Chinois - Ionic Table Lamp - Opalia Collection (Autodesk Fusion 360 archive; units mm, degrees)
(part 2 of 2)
create_component "CreateComponent4"
create_component "CreateComponent5"
create_component "CreateComponent6"
create_component "CreateComponent7"
create_component "CreateComponent8"
remove_body "RemoveBody1"
create_component "CreateComponent9"
create_component "CreateComponent10"
create_component "CreateComponent11"
create_component "CreateComponent12"
create_component "CreateComponent13"
create_component "CreateComponent14"
create_component "CreateComponent15"
create_component "CreateComponent16"
create_component "CreateComponent17"
create_component "CreateComponent18"
remove_body "RemoveBody6"
create_component "CreateComponent19"
create_component "CreateComponent20"
create_component "CreateComponent21"
create_component "CreateComponent22"
create_component "CreateComponent23"
named bodies: "Marble Base", "Rotary Switch", "Coiled - SVT (Blk Fabric)", "Glass Globe", "Metal Housing", "Metal Socket Cover", "Porcelain Socket", "Brass Dial - Dimmer Knob", "Solitaire Petite", "Facet Petite", "Body1", "Body2", "Plastic Insert", "Silicone Gasket", "Oculo Petite", "Balon v2", "Balon v3", "Trove - TL", "Trove - TL (1)", "Neoprene Pad", "2-Pole Plug End", "Rubber Grommet", "Chinois"

design "Trove - TL"
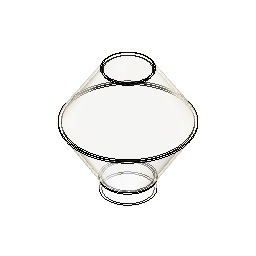
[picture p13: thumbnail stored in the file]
derived_base_feature "Derived Base Feature" bodies "Trove"
hole "Hole1" HoleDepth 88.9 HoleDiameter 44.45 TipAngle 118
sketch "Sketch1" plane through (0, 0, 0) normal (1, 0, 0) x axis (0, 1, 0)
  line L1 (0, 243.0601) -> (0, 247.8226)
  line L2 (-50.8, -12.7122) -> (-50.8, 10.9447)
  line L3 (0, -25.4) -> (0, 243.0601)
  line L4 (-46.0375, -12.7122) -> (-50.8, -12.7122)
  line L5 (-46.0375, -12.7122) -> (-46.0375, 12.3043)
  line L6 (-45.9716, 247.8226) -> (0, 247.8226)
  line L7 (-43.3841, 243.0601) -> (0, 243.0601)
  line L8 (-122.8321, 128.6352) -> (-51.757, 14.2971)
  line L9 (-117.1907, 128.5808) -> (-46.9945, 15.6567)
  line L10 (-48.6353, 246.3754) -> (-122.7993, 132.0392)
  line L11 (-46.0478, 241.6129) -> (-117.1579, 131.9848)
  arc A1 centre (-57.15, 10.9447) radius 6.35 clockwise from (-51.757, 14.2971) to (-50.8, 10.9447)
  arc A2 centre (-52.3875, 12.3043) radius 6.35 clockwise from (-46.9945, 15.6567) to (-46.0375, 12.3043)
  arc A3 centre (-114.4942, 130.257) radius 3.175 between (-117.1579, 131.9848) and (-117.1907, 128.5808)
  arc A4 centre (-120.1356, 130.3114) radius 3.175 between (-122.7993, 132.0392) and (-122.8321, 128.6352)
  arc A5 centre (-45.9716, 244.6476) radius 3.175 between (-45.9716, 247.8226) and (-48.6353, 246.3754)
  arc A6 centre (-43.3841, 239.8851) radius 3.175 clockwise from (-46.0478, 241.6129) to (-43.3841, 243.0601)
  point P3 (0, 247.8226)
  point P4 (0, 243.0601)
  vertical L1
  vertical L3
  tangent L5 A2
  perpendicular L1 L6
  perpendicular L1 L7
  tangent L11 A3
  tangent L9 A3
  tangent L10 A4
  tangent L8 A4
  equal A3 A4
  tangent L6 A5
  tangent L10 A5
  tangent L11 A6
  tangent L7 A6
  dimension "d8" distance P3 P4 = 4.7625
  dimension "d11" radius A2 = 6.35
  dimension "d15" radius A3 = 3.175
  dimension "d16" radius A5 = 3.175
  dimension "d17" radius A6 = 3.175
revolve "Revolve1" sketch "Sketch1" AlongAngle 180 bodies "Trove - TL"
revolve "Revolve2" sketch "Sketch1" AlongAngle -180
component_from_bodies "Body->Comp"
remove_body "RemoveBody2"
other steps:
base_feature "Base Feature" bodies "Trove - TL"
create_component "CreateComponent1"
remove_body "RemoveBody1"
named bodies: "Trove", "Trove - TL"

design "T9-5In"
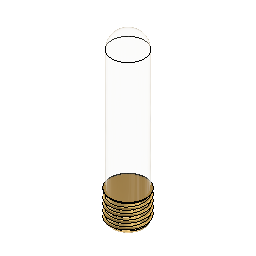
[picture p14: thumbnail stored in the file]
sketch "Sketch1" plane through (0, 0, 0) normal (0, 1, 0) x axis (1, 0, 0)
  line L1 (0, 0) -> (0, -127)
  line L2 (12.7, -127) -> (-12.7, -127)
  line L3 (12.7, -12.7) -> (12.7, -127)
  line L4 (-12.7, -127) -> (-12.7, -12.7)
  arc A1 centre (0, -12.7) radius 12.7 clockwise from (-12.7, -12.7) to (12.7, -12.7)
  point P1 (0, 0)
  point P3 (0, 0)
  coincident P1 P3
  vertical L1
  horizontal L2
  vertical L3
  vertical L4
revolve "Revolve1" sketch "Sketch1" AlongAngle 360 bodies "BU-T10-5-LED-120V"
derived_base_feature "Derived Base Feature" bodies "E26 Base"
move "Move1"
component_from_bodies "Body->Comp"
copy_paste "CutPaste"
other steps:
base_feature "Base Feature" bodies "BU-T10-5-LED-120V"
create_component "CreateComponent1"
create_component "CreateComponent2"
remove_body "RemoveBody1"
remove_instance "RemoveInstance1"
named bodies: "BU-T10-5-LED-120V", "E26 Base"

design "Balon v2"
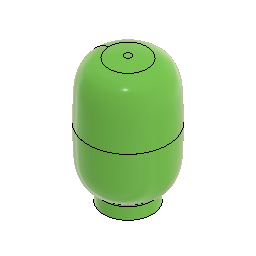
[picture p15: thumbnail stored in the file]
derived_base_feature "Derived Base Feature" bodies "Balon"
work_plane "WorkPlane1" AlongDistance 0
sketch "Sketch1" plane through (0, 0, 0) normal (0, 1, 0) x axis (1, 0, 0)
  line L1 (0, 317.5) -> (0, 2.9083)
  curve K1 (-82.9821, 124.2212) -> (-50.8, 237.8015)
  curve K2 (-51.0925, 237.681) -> (-50.8, 237.8015)
  curve K3 (-51.3855, 237.5558) -> (-51.0925, 237.681)
  curve K4 (-54.7608, 236.0513) -> (-51.3855, 237.5558)
  curve K5 (-57.9615, 234.05) -> (-54.7608, 236.0513)
  curve K6 (-67.2727, 226.749) -> (-57.9615, 234.05)
  curve K7 (-69.0552, 224.2615) -> (-67.2727, 226.749)
  curve K8 (-72.1872, 218.7832) -> (-69.0552, 224.2615)
  curve K9 (-74.1213, 215.1556) -> (-72.1872, 218.7832)
  curve K10 (-78.3031, 204.3965) -> (-74.1213, 215.1556)
  curve K11 (-79.7275, 197.3397) -> (-78.3031, 204.3965)
  curve K12 (-81.3333, 185.4664) -> (-79.7275, 197.3397)
  curve K13 (-81.6254, 178.4008) -> (-81.3333, 185.4664)
  curve K14 (-82.49, 152.2133) -> (-81.6254, 178.4008)
  curve K15 (-82.9821, 136.067) -> (-82.49, 152.2133)
  curve K16 (-82.9821, 124.2212) -> (-82.9821, 136.067)
  curve K17 (50.8, 237.7999) -> (82.9821, 124.2212)
  curve K18 (82.9821, 140.3031) -> (82.9821, 124.2212)
  curve K19 (81.9353, 169.4257) -> (82.9821, 140.3031)
  curve K20 (81.3621, 183.6489) -> (81.9353, 169.4257)
  curve K21 (80.9478, 189.8724) -> (81.3621, 183.6489)
  curve K22 (77.8147, 206.9858) -> (80.9478, 189.8724)
  curve K23 (74.9652, 213.2153) -> (77.8147, 206.9858)
  curve K24 (69.4688, 224.1531) -> (74.9652, 213.2153)
  curve K25 (67.2512, 226.458) -> (69.4688, 224.1531)
  curve K26 (61.5696, 231.3138) -> (67.2512, 226.458)
  curve K27 (57.377, 234.6711) -> (61.5696, 231.3138)
  curve K28 (52.0556, 237.2628) -> (57.377, 234.6711)
  curve K29 (51.4313, 237.5413) -> (52.0556, 237.2628)
  curve K30 (50.8, 237.7999) -> (51.4313, 237.5413)
  line L2 (-50.8, 317.5) -> (-50.8, 237.8015)
  line L3 (50.8, 317.5) -> (50.8, 237.7999)
  line L4 (-19.0713, 6.7501) -> (-19.0713, 6.7501)
  curve K31 (82.9821, 124.1958) -> (40.1509, 7.3012)
  curve K32 (41.8198, 7.6176) -> (40.1509, 7.3012)
  curve K33 (43.2113, 8.0663) -> (41.8198, 7.6176)
  curve K34 (47.0139, 9.2854) -> (43.2113, 8.0663)
  curve K35 (47.3314, 9.3805) -> (47.0139, 9.2854)
  curve K36 (50.1192, 10.3272) -> (47.3314, 9.3805)
  curve K37 (51.833, 11.0085) -> (50.1192, 10.3272)
  curve K38 (57.8313, 14.1895) -> (51.833, 11.0085)
  curve K39 (61.4491, 17.0488) -> (57.8313, 14.1895)
  curve K40 (66.8203, 21.5867) -> (61.4491, 17.0488)
  curve K41 (68.5372, 23.5528) -> (66.8203, 21.5867)
  curve K42 (71.2201, 27.8971) -> (68.5372, 23.5528)
  curve K43 (74.7424, 33.8984) -> (71.2201, 27.8971)
  curve K44 (78.2342, 44.8406) -> (74.7424, 33.8984)
  curve K45 (79.6792, 50.3463) -> (78.2342, 44.8406)
  curve K46 (81.3558, 63.5576) -> (79.6792, 50.3463)
  curve K47 (81.6386, 70.4415) -> (81.3558, 63.5576)
  curve K48 (82.4897, 96.2198) -> (81.6386, 70.4415)
  curve K49 (82.9814, 112.3523) -> (82.4897, 96.2198)
  curve K50 (82.9821, 124.1958) -> (82.9814, 112.3523)
  curve K51 (-40.1501, 7.301) -> (-82.9821, 124.1958)
  curve K52 (-82.9813, 110.5256) -> (-82.9821, 124.1958)
  curve K53 (-82.2545, 88.8594) -> (-82.9813, 110.5256)
  curve K54 (-81.6277, 70.519) -> (-82.2545, 88.8594)
  curve K55 (-81.3572, 64.3441) -> (-81.6277, 70.519)
  curve K56 (-79.4149, 46.8924) -> (-81.3572, 64.3441)
  curve K57 (-76.5204, 38.9768) -> (-79.4149, 46.8924)
  curve K58 (-73.5142, 32.2947) -> (-76.5204, 38.9768)
  curve K59 (-72.5556, 30.3818) -> (-73.5142, 32.2947)
  curve K60 (-69.7914, 25.3691) -> (-72.5556, 30.3818)
  curve K61 (-68.3824, 23.4028) -> (-69.7914, 25.3691)
  curve K62 (-64.5419, 19.5456) -> (-68.3824, 23.4028)
  curve K63 (-62.3002, 17.7646) -> (-64.5419, 19.5456)
  curve K64 (-53.6583, 11.1976) -> (-62.3002, 17.7646)
  curve K65 (-49.6968, 10.1396) -> (-53.6583, 11.1976)
  curve K66 (-43.4141, 8.1331) -> (-49.6968, 10.1396)
  curve K67 (-41.9704, 7.6516) -> (-43.4141, 8.1331)
  curve K68 (-40.1963, 7.3098) -> (-41.9704, 7.6516)
  curve K69 (-40.1732, 7.3054) -> (-40.1963, 7.3098)
  curve K70 (-40.1501, 7.301) -> (-40.1732, 7.3054)
  line L5 (-82.9821, 124.1958) -> (-82.9821, 124.2212)
  line L6 (82.9821, 124.2212) -> (82.9821, 124.1958)
  line L7 (0, 317.5) -> (-50.8, 317.5)
  line L8 (7.2015, 3.048) -> (0, 3.048)
  line L9 (0, 3.048) -> (-7.2015, 3.048)
  arc A1 centre (0, 188.595) radius 185.6867 clockwise from (-7.2015, 3.048) to (-40.1502, 7.301)
  arc A2 centre (0, 188.595) radius 185.6867 clockwise from (40.151, 7.3012) to (7.2015, 3.048)
  point P38 (-40.1502, 7.301)
  point P43 (40.1509, 7.3012)
  point P62 (-40.1501, 7.301)
  point P81 (40.151, 7.3012)
  point P84 (0, 3.048)
  vertical L1
  horizontal L4
  coincident P38 K51
  symmetric L1 A1 A2
  coincident A2 P43
  coincident A1 P62
  coincident K31 P81
  perpendicular L2 L7
  horizontal L8
  coincident L1 P84
  horizontal L9
revolve "Revolve1" sketch "Sketch1" AlongAngle 360
shell "Shell1" innerThickness 3.81
fillet "Fillet1" radius 6.35
offset_faces "OffsetFaces1" distance -50.8
move "Move1"
move "Move2"
component_from_bodies "Body->Comp1"
component_from_bodies "Body->Comp2"
sketch "Sketch2" plane through (0, 0, 0) normal (0, 1, 0) x axis (1, 0, 0)
  line L1 (-85.5221, 124.2212) -> (-85.5221, 124.1961)
  curve K1 (-58.9057, 236.4383) -> (-50.8, 241.7989)
  curve K2 (-50.8, 241.554) -> (-50.8, 241.7989)
  curve K3 (-50.904, 240.933) -> (-50.8, 241.554)
  curve K4 (-51.2936, 240.2837) -> (-50.904, 240.933)
  curve K5 (-51.734, 239.7561) -> (-51.2936, 240.2837)
  curve K6 (-53.328, 238.5038) -> (-51.734, 239.7561)
  curve K7 (-54.0892, 238.1997) -> (-53.328, 238.5038)
  curve K8 (-58.9057, 236.4383) -> (-54.0892, 238.1997)
  curve K9 (-89.3309, 124.2212) -> (-58.9057, 236.4383)
  curve K10 (-62.6336, 234.9735) -> (-58.9057, 236.4383)
  curve K11 (-65.581, 233.1032) -> (-62.6336, 234.9735)
  curve K12 (-73.0224, 227.0019) -> (-65.581, 233.1032)
  curve K13 (-74.8981, 224.836) -> (-73.0224, 227.0019)
  curve K14 (-78.1104, 219.6097) -> (-74.8981, 224.836)
  curve K15 (-80.2663, 215.561) -> (-78.1104, 219.6097)
  curve K16 (-84.0943, 205.8277) -> (-80.2663, 215.561)
  curve K17 (-85.4655, 200.1154) -> (-84.0943, 205.8277)
  curve K18 (-87.4092, 188.5789) -> (-85.4655, 200.1154)
  curve K19 (-87.7349, 182.3889) -> (-87.4092, 188.5789)
  curve K20 (-88.4233, 165.9645) -> (-87.7349, 182.3889)
  curve K21 (-89.328, 138.6964) -> (-88.4233, 165.9645)
  curve K22 (-89.3309, 124.2212) -> (-89.328, 138.6964)
  line L2 (-89.3309, 124.1958) -> (-89.3309, 124.2212)
  curve K23 (-46.5001, 7.301) -> (-89.3309, 124.1958)
  curve K24 (-89.3314, 112.4293) -> (-89.3309, 124.1958)
  curve K25 (-88.8181, 95.3068) -> (-89.3314, 112.4293)
  curve K26 (-88.346, 81.2892) -> (-88.8181, 95.3068)
  curve K27 (-88.0298, 70.4902) -> (-88.346, 81.2892)
  curve K28 (-87.1514, 58.328) -> (-88.0298, 70.4902)
  curve K29 (-86.3326, 50.6119) -> (-87.1514, 58.328)
  curve K30 (-81.0932, 33.6688) -> (-86.3326, 50.6119)
  curve K31 (-77.3163, 27.4309) -> (-81.0932, 33.6688)
  curve K32 (-74.8955, 23.6666) -> (-77.3163, 27.4309)
  curve K33 (-73.5108, 22.0741) -> (-74.8955, 23.6666)
  curve K34 (-70.2346, 19.0457) -> (-73.5108, 22.0741)
  curve K35 (-64.8094, 14.3548) -> (-70.2346, 19.0457)
  curve K36 (-56.6696, 10.3041) -> (-64.8094, 14.3548)
  curve K37 (-54.0053, 9.483) -> (-56.6696, 10.3041)
  curve K38 (-49.1487, 7.9411) -> (-54.0053, 9.483)
  curve K39 (-48.3482, 7.6526) -> (-49.1487, 7.9411)
  curve K40 (-46.5001, 7.301) -> (-48.3482, 7.6526)
  line L3 (0, 266.7) -> (0, 0)
  line L4 (0, 3.048) -> (-7.7894, 3.048)
  line L5 (-50.8, 266.7) -> (-50.8, 241.7989)
  line L6 (0, 266.7) -> (-50.8, 266.7)
  arc A1 centre (-6.9779, 188.7329) radius 185.6867 clockwise from (-7.7894, 3.048) to (-46.5001, 7.301)
  point P1 (0, 0)
  point P44 (0, 0)
  point P46 (0, 3.048)
  point P5 (-50.8, 241.554)
  point P49 (0, 266.7)
  coincident P1 P44
  coincident L3 P46
  coincident P5 L5
  coincident L3 P49
revolve "Revolve2" sketch "Sketch2" AlongAngle 360 bodies "Balon v3"
shell "Shell2" innerThickness 3.81
component_from_bodies "Body->Comp3"
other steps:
base_feature "Base Feature1" bodies "Balon"
base_feature "Base Feature1" bodies "Balon v3"
base_feature "Base Feature1" bodies "Balon v2"
create_component "CreateComponent1"
remove_body "RemoveBody1"
create_component "CreateComponent2"
remove_body "RemoveBody2"
create_component "CreateComponent3"
remove_body "RemoveBody3"
named bodies: "Balon", "Balon v2", "Balon v3"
